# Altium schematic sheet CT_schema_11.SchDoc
size 147 x 119 mm
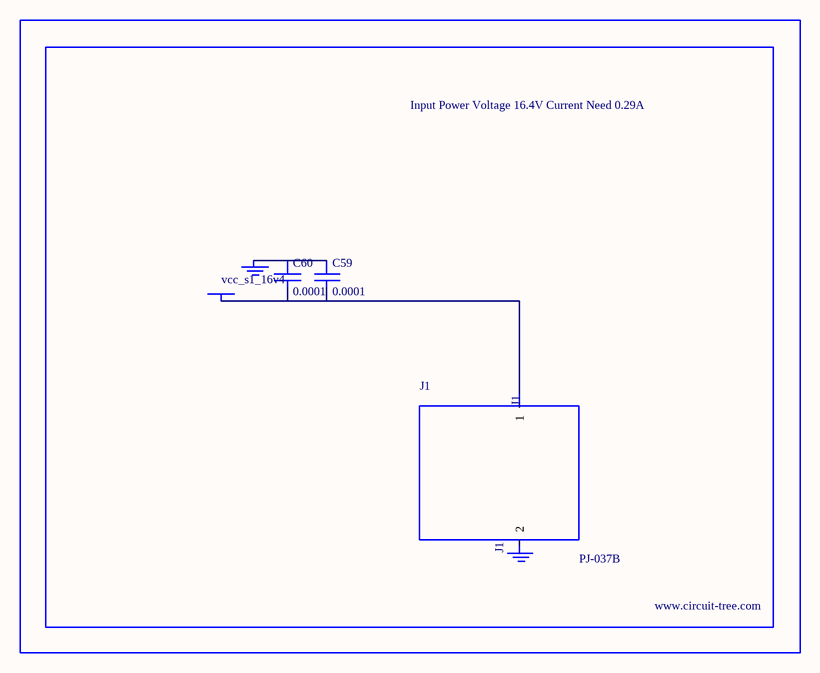
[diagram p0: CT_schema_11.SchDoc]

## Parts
BORDER10  (no value)
C59  0.0001  [EXV-9H]
C60  0.0001  [EXV-9H]
GND_INSTANCE_10_0  (no value)
GND_INSTANCE_10_1  (no value)
J1  PJ-037B  [PJ-037B_PACKAGE]
POWER_INSTANCE_10_0  vcc_s1_16v4

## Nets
NetC59_1: C59.1 C60.1 GND_INSTANCE_10_0.0(GND)
NetC59_2: C59.2 C60.2 J1.1 POWER_INSTANCE_10_0.0(PWR)

Not connected (* = marked no-connect by the designer): GND_INSTANCE_10_1 0(GND); J1 2

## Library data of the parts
BORDER10 = BORDER_PAGE10
C59 C60 = EDK107M035A9HAA
GND_INSTANCE_10_0 GND_INSTANCE_10_1 = GND
POWER_INSTANCE_10_0 = PWR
